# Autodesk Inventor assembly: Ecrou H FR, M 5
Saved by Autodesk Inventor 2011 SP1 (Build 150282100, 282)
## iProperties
Created: 2010-12
Part Number: Ecrou H FR, M 5
Document SubType Name: Assembly
Designer: eric
Author: eric
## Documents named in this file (3)
- D:\eduinventor\maquettesaip2011\machineàpain\Workspace\Ecrou H FR, M 5.iam
- D:\eduinventor\maquettesaip2011\machineàpain\Workspace\Ecrou-Ecrou H FR, M 5.ipt
- D:\eduinventor\maquettesaip2011\machineàpain\Workspace\Bague-Ecrou H FR, M 5.ipt
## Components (2 placed, 2 different names)
1. Ecrou-Ecrou H FR, M 5:1
2. Bague-Ecrou H FR, M 5:1
